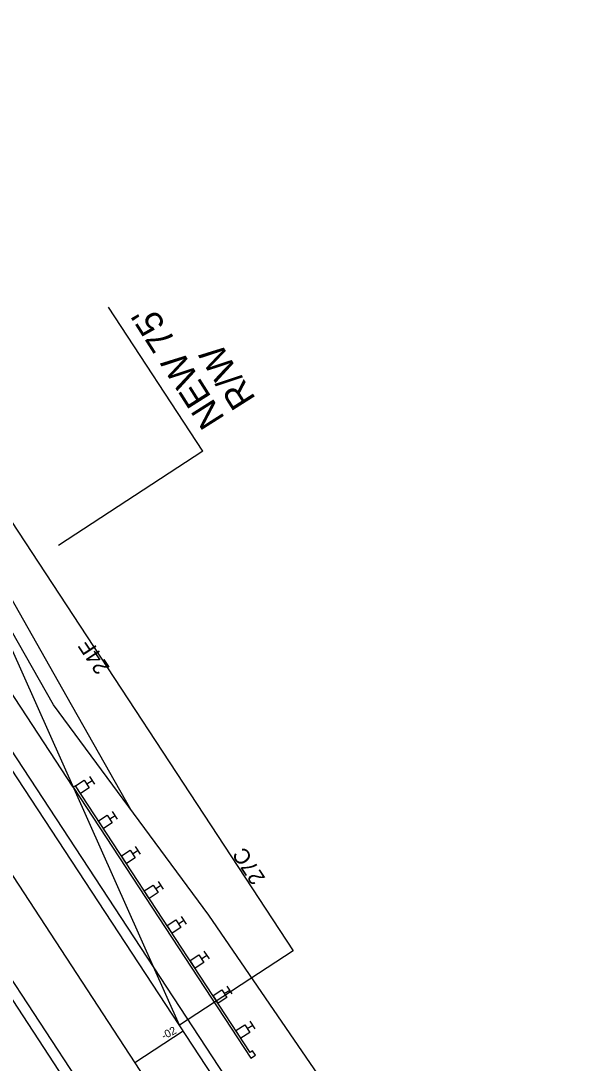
# Model space of a CAD drawing. Extents: x 1551641 to 1624343, y 1119533 to 1136600.
# Drawn here: x 1552738.3 to 1552843.3, y 1134110 to 1134309.5 of the extents above; entities that cross this region are included whole.
import ezdxf

# ---------------------------------------------------------------- set-up
doc = ezdxf.new("R2010")
doc.units = 0
for name, color, linetype in [('RD_HC_CL_Rel', 7, 'Continuous'), ('RD_PD_ALT1_TX', 7, 'Continuous'), ('RD_PD_CstnLmt', 7, 'Continuous'), ('RD_PD_CstnLmt_TX', 7, 'Continuous'), ('RD_PD_DR_ErosCtrl', 7, 'Continuous'), ('RD_PD_Final_TrvlWay', 7, 'Continuous'), ('RD_PD_GR', 7, 'Continuous'), ('RD_PD_PaveShd', 7, 'Continuous'), ('RD_PD_RW', 7, 'Continuous'), ('RD_Sketch8', 7, 'Continuous')]:
    doc.layers.add(name, color=color, linetype=linetype)

msp = doc.modelspace()

# ---------------------------------------------------------------- linework, layer by layer
at = {"layer": 'RD_HC_CL_Rel'}
msp.add_line((1552832.44, 1133999.68), (1552472.39, 1134549.2), dxfattribs=at)
at = {"layer": 'RD_PD_ALT1_TX'}
msp.add_line((1552760.1, 1134110.09), (1552769.3, 1134116.12), dxfattribs=at)
at = {"layer": 'RD_PD_CstnLmt'}
for p, q in [((1552744.5, 1134178.56), (1552719.76, 1134222.13)), ((1552774.24, 1134138.26), (1552744.5, 1134178.56)), ((1552802.49, 1134097), (1552774.24, 1134138.26))]:
    msp.add_line(p, q, dxfattribs=at)
at = {"layer": 'RD_PD_DR_ErosCtrl'}
for p, q in [((1552747.11, 1134180.04), (1552722.35, 1134223.65)), ((1552759.37, 1134158.41), (1552747.11, 1134180.04))]:
    msp.add_line(p, q, dxfattribs=at)
at = {"layer": 'RD_PD_Final_TrvlWay'}
for p, q in [((1552841.65, 1134005.71), (1552481.59, 1134555.23)), ((1552823.24, 1133993.65), (1552463.19, 1134543.17))]:
    msp.add_line(p, q, dxfattribs=at)
at = {"layer": 'RD_PD_GR'}
for p, q in [((1552748.3, 1134162.77), (1552713.11, 1134216.47)), ((1552752.4, 1134163.36), (1552751.44, 1134164.82)), ((1552748.72, 1134163.04), (1552748.3, 1134162.77)), ((1552748.3, 1134162.77), (1552782.28, 1134110.91)), ((1552748.72, 1134163.04), (1552750.39, 1134164.14)), ((1552749.68, 1134161.58), (1552748.72, 1134163.04)), ((1552782.15, 1134112.02), (1552748.72, 1134163.04)), ((1552751.35, 1134162.67), (1552749.68, 1134161.58)), ((1552750.39, 1134164.14), (1552751.35, 1134162.67)), ((1552750.87, 1134163.41), (1552751.92, 1134164.09)), ((1552753.1, 1134156.35), (1552754.78, 1134157.45)), ((1552754.78, 1134157.45), (1552755.74, 1134155.98)), ((1552755.26, 1134156.71), (1552756.3, 1134157.4)), ((1552756.78, 1134156.67), (1552755.82, 1134158.13)), ((1552754.06, 1134154.89), (1552753.1, 1134156.35)), ((1552755.74, 1134155.98), (1552754.06, 1134154.89)), ((1552757.49, 1134149.66), (1552759.16, 1134150.75)), ((1552759.16, 1134150.75), (1552760.12, 1134149.29)), ((1552759.64, 1134150.02), (1552760.69, 1134150.71)), ((1552761.17, 1134149.98), (1552760.21, 1134151.44)), ((1552758.45, 1134148.19), (1552757.49, 1134149.66)), ((1552760.12, 1134149.29), (1552758.45, 1134148.19)), ((1552765.55, 1134143.28), (1552764.59, 1134144.75)), ((1552761.87, 1134142.97), (1552763.55, 1134144.06)), ((1552762.83, 1134141.5), (1552761.87, 1134142.97)), ((1552764.51, 1134142.6), (1552762.83, 1134141.5)), ((1552763.55, 1134144.06), (1552764.51, 1134142.6)), ((1552764.03, 1134143.33), (1552765.07, 1134144.02)), ((1552766.26, 1134136.28), (1552767.93, 1134137.37)), ((1552767.93, 1134137.37), (1552768.89, 1134135.91)), ((1552768.41, 1134136.64), (1552769.46, 1134137.32)), ((1552769.94, 1134136.59), (1552768.98, 1134138.06)), ((1552767.22, 1134134.81), (1552766.26, 1134136.28)), ((1552768.89, 1134135.91), (1552767.22, 1134134.81)), ((1552770.64, 1134129.58), (1552772.32, 1134130.68)), ((1552772.32, 1134130.68), (1552773.27, 1134129.22)), ((1552772.8, 1134129.95), (1552773.84, 1134130.63)), ((1552774.32, 1134129.9), (1552773.36, 1134131.37)), ((1552771.6, 1134128.12), (1552770.64, 1134129.58)), ((1552773.27, 1134129.22), (1552771.6, 1134128.12)), ((1552778.7, 1134123.21), (1552777.75, 1134124.67)), ((1552775.03, 1134122.89), (1552776.7, 1134123.99)), ((1552775.99, 1134121.43), (1552775.03, 1134122.89)), ((1552777.66, 1134122.52), (1552775.99, 1134121.43)), ((1552776.7, 1134123.99), (1552777.66, 1134122.52)), ((1552777.18, 1134123.26), (1552778.23, 1134123.94)), ((1552779.41, 1134116.2), (1552781.08, 1134117.3)), ((1552781.08, 1134117.3), (1552782.04, 1134115.83)), ((1552781.56, 1134116.57), (1552782.61, 1134117.25)), ((1552783.09, 1134116.52), (1552782.13, 1134117.98)), ((1552780.37, 1134114.74), (1552779.41, 1134116.2)), ((1552782.04, 1134115.83), (1552780.37, 1134114.74)), ((1552782.57, 1134112.29), (1552782.15, 1134112.02)), ((1552782.28, 1134110.91), (1552783.12, 1134111.46)), ((1552783.12, 1134111.46), (1552782.57, 1134112.29))]:
    msp.add_line(p, q, dxfattribs=at)
at = {"layer": 'RD_PD_PaveShd'}
for p, q in [((1552843.32, 1134006.81), (1552718.03, 1134198.02)), ((1552821.57, 1133992.56), (1552697.38, 1134182.1))]:
    msp.add_line(p, q, dxfattribs=at)
at = {"layer": 'RD_PD_RW'}
for q in [(1552755.02, 1134254.69), (1552745.46, 1134209.07)]:
    msp.add_line((1552773.06, 1134227.16), q, dxfattribs=at)
at = {"layer": 'RD_Sketch8'}
for p, q in [((1552702.65, 1134265.28), (1552790.34, 1134131.45)), ((1552768.59, 1134117.2), (1552702.65, 1134265.28)), ((1552790.34, 1134131.45), (1552768.59, 1134117.2))]:
    msp.add_line(p, q, dxfattribs=at)

# ---------------------------------------------------------------- texts
at = {"layer": 'RD_PD_ALT1_TX'}
msp.add_text('-02', height=1.5, rotation=27.7864, dxfattribs=at).set_placement((1552765.62, 1134114.4))
at = {"layer": 'RD_PD_CstnLmt_TX'}
for s, p in [('24F', (1552755.37, 1134185.68)), ('27C', (1552785.11, 1134145.39))]:
    msp.add_text(s, height=3, rotation=123.2337, dxfattribs=at).set_placement(p)
at = {"layer": 'RD_PD_RW'}
for s, p in [("NEW 75' ", (1552777.39, 1134233.42)), ('R/W', (1552783.3, 1134237.16))]:
    msp.add_text(s, height=5, rotation=122.3587, dxfattribs=at).set_placement(p)

doc.saveas('drawing.dxf')
